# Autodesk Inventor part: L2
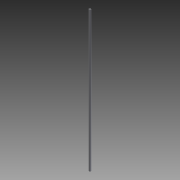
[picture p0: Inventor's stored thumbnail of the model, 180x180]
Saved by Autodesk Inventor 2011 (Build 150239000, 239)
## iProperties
Created: 2014-02
Part Number: L2
Document SubType Name: Modeling
Designer: Evgeny
Density: 1 g/cm^3
Author: Evgeny
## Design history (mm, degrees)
sketch "Эскиз1"
  geometry: C1 r 4 at (0, 0); 1 further point
  constraints: 1 centre point, 1 coincident
  dimensions: "d0" = 8 diameter of C1
extrude "Выдавливание1" new body sketch "Эскиз1" distance "d1" = 587; taper "d2" = 0 deg
feature "Оболочка1" dims "d3" = 1
node "Твердое тело1"
